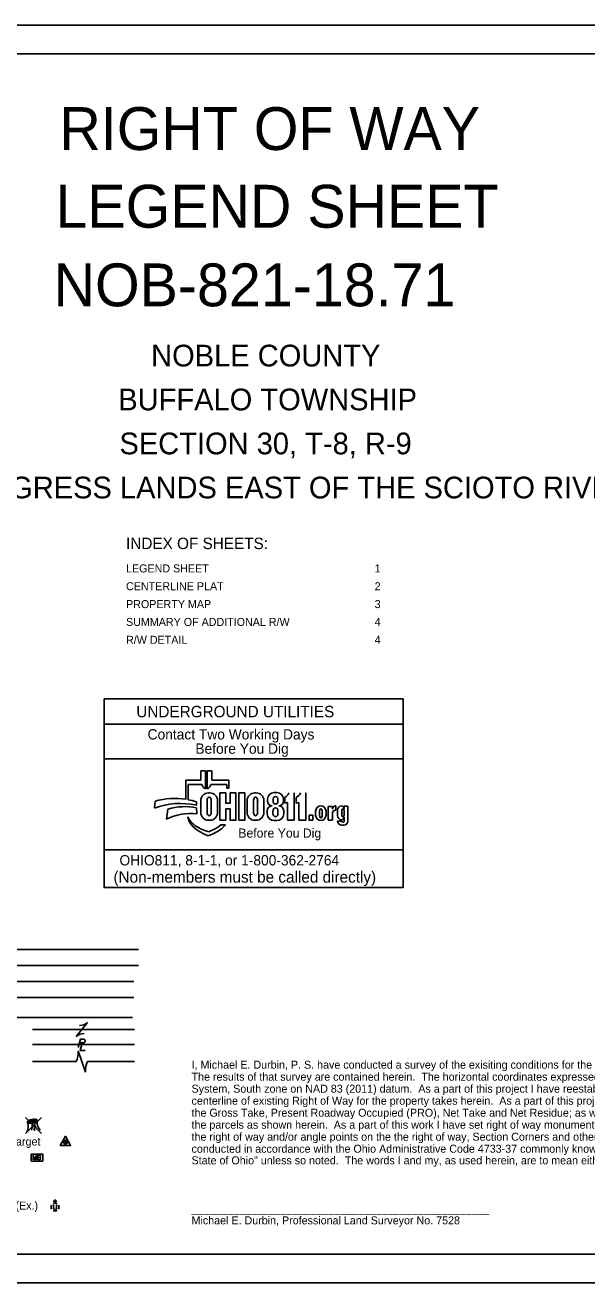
# Model space of a CAD drawing. Extents: x 0 to 34, y 0 to 22.
# Drawn here: x 11.93 to 21.75, y 0 to 22 of the extents above; entities that cross this region are included whole.
import ezdxf

# ---------------------------------------------------------------- set-up
doc = ezdxf.new("R2010")
doc.units = 0
for name, color, linetype in [('SH_Border', 7, 'Continuous'), ('SH_Cut_Line', 7, 'Continuous'), ('SH_Data', 7, 'Continuous'), ('SH_Text', 7, 'Continuous')]:
    doc.layers.add(name, color=color, linetype=linetype)

msp = doc.modelspace()

# ---------------------------------------------------------------- linework, layer by layer
at = {"layer": 'SH_Border'}
msp.add_lwpolyline([(1.5, 21.5), (33.5, 21.5), (33.5, 0.5), (1.5, 0.5)], close=True, dxfattribs=at)
at = {"layer": 'SH_Cut_Line'}
msp.add_lwpolyline([(0, 0), (34, 0), (34, 22), (0, 22)], close=True, dxfattribs=at)
at = {"layer": 'SH_Data'}
for p, q in [((15.08, 8.958), (15, 8.958)), ((15, 8.958), (15, 8.792)), ((15.08, 8.642), (15.08, 8.958)), ((15.192, 8.958), (15.111, 8.958)), ((15.111, 8.958), (15.111, 8.642)), ((15.192, 8.792), (15.192, 8.958)), ((15, 8.792), (14.737, 8.792)), ((14.737, 8.792), (14.737, 8.457)), ((14.775, 8.451), (14.775, 8.715)), ((14.775, 8.715), (15.016, 8.715)), ((15.176, 8.715), (15.454, 8.715)), ((15.489, 8.792), (15.192, 8.792)), ((15.454, 8.715), (15.454, 8.652)), ((15.454, 8.652), (15.489, 8.652)), ((15.489, 8.652), (15.489, 8.792)), ((14.202, 8.423), (14.188, 8.307)), ((14.921, 8.356), (14.921, 8.414)), ((14.999, 8.437), (14.999, 8.225)), ((15.108, 8.242), (15.108, 8.425)), ((15.157, 8.571), (15.132, 8.571)), ((15.182, 8.425), (15.182, 8.242)), ((15.291, 8.225), (15.291, 8.437)), ((15.435, 8.569), (15.333, 8.569)), ((15.333, 8.569), (15.333, 8.091)), ((15.809, 8.437), (15.809, 8.225)), ((15.918, 8.242), (15.918, 8.425)), ((15.968, 8.571), (15.943, 8.571)), ((15.993, 8.425), (15.993, 8.242)), ((16.101, 8.225), (16.101, 8.437)), ((16.166, 8.463), (16.166, 8.427)), ((16.265, 8.41), (16.265, 8.469)), ((16.329, 8.577), (16.28, 8.577)), ((16.346, 8.469), (16.346, 8.41)), ((16.443, 8.427), (16.443, 8.463)), ((16.466, 8.389), (16.466, 8.491)), ((16.514, 8.091), (16.514, 8.403)), ((16.633, 8.569), (16.633, 8.091)), ((16.666, 8.389), (16.666, 8.491)), ((16.714, 8.091), (16.714, 8.403)), ((16.833, 8.569), (16.833, 8.091)), ((14.423, 8.288), (14.401, 8.109)), ((14.774, 8.151), (14.779, 8.125)), ((14.931, 8.205), (14.922, 8.311)), ((15.435, 8.091), (15.435, 8.293)), ((16.16, 8.257), (16.16, 8.206)), ((16.261, 8.197), (16.261, 8.258)), ((16.346, 8.258), (16.346, 8.197)), ((16.449, 8.206), (16.449, 8.257)), ((17.006, 8.182), (17.006, 8.25)), ((17.074, 8.181), (17.074, 8.25)), ((17.122, 8.25), (17.122, 8.181)), ((17.189, 8.25), (17.189, 8.182)), ((17.301, 8.335), (17.228, 8.335)), ((17.228, 8.335), (17.228, 8.091)), ((17.301, 8.288), (17.301, 8.335)), ((17.301, 8.091), (17.301, 8.219)), ((17.351, 8.268), (17.362, 8.268)), ((17.362, 8.342), (17.356, 8.342)), ((17.362, 8.268), (17.362, 8.342)), ((17.39, 8.17), (17.39, 8.274)), ((17.463, 8.183), (17.463, 8.26)), ((17.505, 8.29), (17.505, 8.336)), ((17.505, 8.336), (17.57, 8.336)), ((17.505, 8.26), (17.505, 8.183)), ((17.505, 8.078), (17.505, 8.147)), ((17.57, 8.336), (17.57, 8.078)), ((15.139, 7.89), (15.05, 7.921)), ((15.132, 8.091), (15.157, 8.091)), ((15.333, 8.091), (15.435, 8.091)), ((15.432, 8.011), (15.347, 8.011)), ((15.43, 8.009), (15.432, 8.011)), ((15.943, 8.091), (15.968, 8.091)), ((16.281, 8.085), (16.328, 8.085)), ((16.633, 8.091), (16.514, 8.091)), ((16.833, 8.091), (16.714, 8.091)), ((17.228, 8.091), (17.301, 8.091)), ((17.39, 8.078), (17.463, 8.078)), ((17.501, 8.008), (17.46, 8.008)), ((15.074, 7.845), (15.13, 7.82)), ((15.13, 7.82), (15.225, 7.861)), ((15.2, 7.917), (15.139, 7.89)), ((18.536, 6.913), (13.311, 6.913))]:
    msp.add_line(p, q, dxfattribs=at)
for points in [[(13.311, 10.213), (18.536, 10.213), (18.536, 9.773), (13.311, 9.773)], [(13.311, 9.773), (18.536, 9.773), (18.536, 9.168), (13.311, 9.168)], [(13.311, 9.168), (18.536, 9.168), (18.536, 7.573), (13.311, 7.573)], [(16.891, 8.181), (16.957, 8.181), (16.957, 8.091), (16.891, 8.091)], [(13.311, 7.573), (18.536, 7.573), (18.536, 6.913), (13.311, 6.913)]]:
    msp.add_lwpolyline(points, close=True, dxfattribs=at)
for points in [[(15.435, 8.293), (15.511, 8.293), (15.511, 8.091), (15.613, 8.091), (15.613, 8.569), (15.511, 8.569), (15.511, 8.389), (15.435, 8.389), (15.435, 8.569)], [(15.663, 8.091), (15.766, 8.091), (15.766, 8.569), (15.663, 8.569), (15.663, 8.091)], [(16.247, 8.343), (16.247, 8.343)], [(16.362, 8.343), (16.362, 8.343)]]:
    msp.add_lwpolyline(points, dxfattribs=at)
for centre, radius, start, end in [((15.152, 8.77), 0.147, 201.9296, 240.7469), ((15.04, 8.77), 0.147, 299.2531, 338.0704), ((14.64, 7.053), 1.332, 77.8238, 109.8274), ((14.546, 7.249), 1.224, 81.0007, 106.3144), ((14.546, 7.249), 1.224, 72.1402, 79.2074), ((15.132, 8.437), 0.134, 90, 180), ((15.157, 8.437), 0.134, 0, 90), ((15.943, 8.437), 0.134, 90, 180), ((15.968, 8.437), 0.134, 0, 90), ((16.28, 8.463), 0.114, 90, 180), ((16.25, 8.427), 0.0837, 180, 268.1442), ((16.329, 8.463), 0.114, 0, 90), ((16.359, 8.427), 0.0837, 272.2058, 0), ((16.415, 8.613), 0.132, 292.5572, 340.7355), ((16.454, 8.521), 0.132, 275.1733, 297.0931), ((16.615, 8.613), 0.132, 292.5572, 340.7355), ((16.654, 8.521), 0.132, 275.1733, 297.0931), ((14.829, 7.261), 0.95, 83.8248, 116.8021), ((14.722, 7.236), 1.094, 79.44, 105.8467), ((15.054, 8.259), 0.3, 201.0457, 232.5314), ((15.132, 8.225), 0.134, 180, 270), ((15.157, 8.225), 0.134, 270, 0), ((15.943, 8.225), 0.134, 180, 270), ((15.968, 8.225), 0.134, 270, 0), ((16.247, 8.257), 0.0865, 90, 180), ((16.281, 8.206), 0.121, 180, 270), ((16.328, 8.206), 0.121, 270, 0), ((16.362, 8.257), 0.0865, 0, 90), ((17.102, 8.25), 0.0956, 92.5886, 180), ((17.102, 8.182), 0.0956, 180, 267.4114), ((17.093, 8.25), 0.0956, 0, 87.4114), ((17.093, 8.182), 0.0956, 272.5886, 0), ((17.356, 8.288), 0.0548, 90, 180), ((17.351, 8.219), 0.0493, 90, 180), ((17.459, 8.274), 0.0686, 92.6865, 180), ((17.46, 8.17), 0.0692, 180, 265.7132), ((17.459, 8.147), 0.0467, 264.7825, 0), ((17.453, 8.29), 0.0524, 0, 86.9262), ((14.99, 8.161), 0.214, 189.6817, 216.0884), ((15.189, 8.306), 0.461, 216.0884, 235.7167), ((15.342, 8.634), 0.773, 232.5314, 241.794), ((15.438, 8.671), 0.903, 235.7167, 246.2325), ((15.214, 8.397), 0.504, 241.794, 250.9821), ((14.986, 8.411), 0.538, 293.4582, 312.0712), ((14.986, 8.411), 0.599, 293.4582, 317.8286), ((17.46, 8.078), 0.0699, 180, 270), ((17.501, 8.078), 0.0699, 270, 0)]:
    msp.add_arc(centre, radius, start, end, dxfattribs=at)
for centre, major_axis, ratio, start_param, end_param in [((15.145, 8.425), (0, 0.0723), 0.514403, 4.712389, 7.853982), ((15.956, 8.425), (0, 0.0723), 0.514403, 4.712389, 7.853982), ((16.305, 8.469), (0.0404, 0), 0.969373, 0, 3.141593), ((16.305, 8.41), (0.0404, 0), 0.818453, 3.141593, 6.283185), ((15.145, 8.242), (0, 0.0723), 0.514403, 1.570796, 4.712389), ((15.956, 8.242), (0, 0.0723), 0.514403, 1.570796, 4.712389), ((16.304, 8.258), (0, 0.0535), 0.794529, 4.712389, 7.853982), ((16.304, 8.197), (0.0425, 0), 0.959837, 3.141593, 6.283185), ((17.098, 8.25), (0, 0.0434), 0.553236, 4.712389, 7.853982), ((17.098, 8.181), (0, 0.046), 0.522014, 1.570796, 4.712389), ((17.484, 8.26), (0, 0.0275), 0.777179, 4.712389, 7.853982), ((17.484, 8.183), (0, 0.0275), 0.777179, 1.570796, 4.712389), ((17.484, 8.078), (0.0214, 0), 0.959012, 3.141593, 6.283185)]:
    msp.add_ellipse(centre, major_axis=major_axis, ratio=ratio, start_param=start_param, end_param=end_param, dxfattribs=at)
at = {"layer": 'SH_Text'}
for p, q in [((10.425, 5.832), (13.909, 5.832)), ((10.425, 5.552), (13.909, 5.552)), ((9.925, 5.272), (13.825, 5.272)), ((9.925, 4.992), (13.825, 4.992)), ((9.457, 4.642), (13.807, 4.642)), ((12.055, 4.432), (13.837, 4.432)), ((12.82, 4.312), (13.02, 4.552)), ((12.92, 4.432), (12.92, 4.432)), ((12.878, 4.197), (12.943, 4.197)), ((12.055, 4.167), (13.837, 4.167)), ((12.855, 4.056), (12.985, 3.688)), ((12.918, 4.165), (12.918, 4.165)), ((12.055, 3.872), (12.82, 3.872)), ((12.92, 3.872), (12.92, 3.872)), ((13.02, 3.872), (13.837, 3.872)), ((11.934, 2.891), (12.212, 2.613)), ((12.212, 2.891), (11.934, 2.613)), ((12.073, 2.752), (12.073, 2.752)), ((12.073, 2.752), (12.073, 2.752)), ((12.134, 2.192), (12.134, 2.192)), ((12.483, 1.427), (12.419, 1.427)), ((12.424, 1.368), (12.424, 1.299)), ((12.451, 1.395), (12.451, 1.459)), ((12.451, 1.325), (12.451, 1.325)), ((12.478, 1.368), (12.478, 1.299))]:
    msp.add_line(p, q, dxfattribs=at)
for points in [[(12.857, 4.117), (12.896, 4.265), (12.948, 4.265)], [(12.932, 4.213), (12.892, 4.066), (12.979, 4.066)], [(12.069, 2.152), (12.069, 2.232), (12.098, 2.152), (12.126, 2.232), (12.126, 2.152)], [(12.185, 2.195), (12.188, 2.198), (12.19, 2.2), (12.191, 2.202), (12.192, 2.203), (12.193, 2.206), (12.194, 2.208), (12.195, 2.212), (12.195, 2.214), (12.195, 2.217), (12.194, 2.22), (12.193, 2.223), (12.191, 2.226), (12.188, 2.229), (12.186, 2.23), (12.184, 2.23), (12.181, 2.232), (12.15, 2.232), (12.15, 2.152), (12.185, 2.152), (12.189, 2.154), (12.193, 2.157), (12.196, 2.162), (12.198, 2.168), (12.199, 2.174), (12.199, 2.178), (12.198, 2.181), (12.195, 2.187), (12.192, 2.191), (12.185, 2.195), (12.15, 2.195)]]:
    msp.add_lwpolyline(points, dxfattribs=at)
for points in [[(12.542, 2.402), (12.722, 2.402), (12.632, 2.563)], [(12.034, 2.253), (12.234, 2.253), (12.234, 2.131), (12.034, 2.131)]]:
    msp.add_lwpolyline(points, close=True, dxfattribs=at)
for radius in [0.035, 0.008]:
    msp.add_circle((12.632, 2.46), radius, dxfattribs=at)
for centre, radius, start, end in [((12.862, 4.767), 0.267, 273.6945, 306.337), ((12.979, 4.097), 0.267, 93.6945, 126.337), ((12.943, 4.231), 0.0345, 270.471, 81.3281), ((12.523, 4.023), 0.334, 332.9422, 5.5848), ((13.317, 3.72), 0.334, 152.9422, 185.5848), ((11.781, 2.734), 0.2, 331.5338, 20.9269), ((11.797, 2.753), 0.253, 340.7938, 3.5481), ((12.268, 2.712), 0.182, 178.7926, 197.1224), ((12.398, 2.855), 0.316, 194.9653, 212.1216), ((12.353, 2.809), 0.215, 171.4106, 219.9194), ((12.451, 1.325), 0.07, 150.0184, 209.9816), ((12.451, 1.325), 0.07, 60.0184, 120.0157), ((12.451, 1.325), 0.07, 330.0184, 29.9816), ((12.451, 1.325), 0.07, 239.9843, 299.9816), ((12.451, 1.312), 0.03, 205.1924, 334.8076)]:
    msp.add_arc(centre, radius, start, end, dxfattribs=at)
for major_axis in [(0.0868, 0.0187), (0.0651, 0.0141), (0.0488, 0.0105), (0.0275, 0.0059), (0.0154, 0.0033)]:
    msp.add_ellipse((12.054, 2.827), major_axis=major_axis, ratio=0.36865, dxfattribs=at)

# ---------------------------------------------------------------- texts
at = {"layer": 'SH_Data'}
for s, height, p in [('RIGHT OF WAY', 0.75, (12.527, 19.816)), ('LEGEND SHEET', 0.75, (12.458, 18.457)), ('NOB-821-18.71', 0.75, (12.425, 17.082)), ('NOBLE COUNTY', 0.38, (14.13, 16.03)), ('BUFFALO TOWNSHIP', 0.38, (13.556, 15.262)), ('SECTION 30, T-8, R-9', 0.38, (13.576, 14.493)), ('INDEX OF SHEETS:', 0.2, (13.692, 12.835)), ('LEGEND SHEET', 0.14, (13.692, 12.427)), ('1', 0.14, (18.038, 12.427)), ('CENTERLINE PLAT', 0.14, (13.692, 12.115)), ('2', 0.14, (18.038, 12.115)), ('PROPERTY MAP', 0.14, (13.692, 11.803)), ('3', 0.14, (18.038, 11.803)), ('SUMMARY OF ADDITIONAL R/W', 0.14, (13.692, 11.491)), ('4', 0.14, (18.038, 11.491)), ('R/W DETAIL', 0.14, (13.692, 11.178)), ('4', 0.14, (18.038, 11.18)), ('UNDERGROUND UTILITIES', 0.2, (13.871, 9.893)), ('Contact Two Working Days', 0.18, (14.069, 9.505)), ('Before You Dig', 0.18, (14.904, 9.255)), ('Before You Dig', 0.15972, (15.655, 7.788)), ('OHIO811, 8-1-1, or 1-800-362-2764', 0.18, (13.577, 7.302)), ('(Non-members must be called directly)', 0.2, (13.472, 7))]:
    msp.add_text(s, height=height, dxfattribs=at).set_placement(p)
at = {"layer": 'SH_Text'}
for s, height, p in [('CONGRESS LANDS EAST OF THE SCIOTO RIVER', 0.38, (10.536, 13.722)), ('I, Michael E. Durbin, P. S. have conducted a survey of the exisiting conditions for the Ohio Department of Transportation in December 2021. ', 0.14, (14.837, 3.746)), ('The results of that survey are contained herein.  The horizontal coordinates expressed herein are based on the Ohio State Plane Coordinate ', 0.14, (14.837, 3.536)), ('System, South zone on NAD 83 (2011) datum.  As a part of this project I have reestablished the locations of the existing property lines and ', 0.14, (14.837, 3.326)), ('centerline of existing Right of Way for the property takes herein.  As a part of this project I have established the proposed property lines, calculated', 0.14, (14.837, 3.116)), ('the Gross Take, Present Roadway Occupied (PRO), Net Take and Net Residue; as well as prepared the legal descriptions necessary to acquire', 0.14, (14.837, 2.906)), ('the parcels as shown herein.  As a part of this work I have set right of way monuments at property corners, property line intersections, points along', 0.14, (14.837, 2.696)), ('Wetland (Pr)         , Grass (Pr)            , Aerial Target    ', 0.14, (7.909, 2.402)), ('the right of way and/or angle points on the the right of way, Section Corners and other points shown herein.  All of my work contained herein was', 0.14, (14.837, 2.486)), ('conducted in accordance with the Ohio Administrative Code 4733-37 commonly known as "Minimum Standards for Boundary Surveys in the ', 0.14, (14.837, 2.276)), ('State of Ohio" unless so noted.  The words I and my, as used herein, are to mean either myself or someone working under my direct supervision.', 0.14, (14.837, 2.073)), ('Water Valve (Ex)         , Utility Valve Unknown (Ex.)', 0.14, (7.909, 1.282)), ('__________________________________________________', 0.14, (14.837, 1.233)), ('Michael E. Durbin, Professional Land Surveyor No. 7528                               ', 0.14, (14.837, 1.023))]:
    msp.add_text(s, height=height, dxfattribs=at).set_placement(p)

doc.saveas('drawing.dxf')
